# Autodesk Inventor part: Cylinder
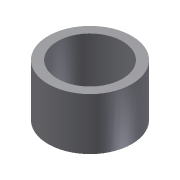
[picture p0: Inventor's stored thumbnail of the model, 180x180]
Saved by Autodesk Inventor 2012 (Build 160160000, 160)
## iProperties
Created: 2010-05
Part Number: Cylinder
Document SubType Name: Modeling
Designer: CADSoft
Density: 1 g/cm^3
Material: Default
Author: CADSoft
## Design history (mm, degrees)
sketch "Sketch1"
  geometry: C1 r 87.5 at (0, 0); C2 r 112.5 at (0, 0); 1 further point
  constraints: 2 centre point, 2 coincident
  dimensions: "d0" = 175 diameter of C1; "d1" = 225 diameter of C2
extrude "Extrusion1" new body sketch "Sketch1" distance "d2" = 140; taper "d3" = 0 deg
body "Solid1"
